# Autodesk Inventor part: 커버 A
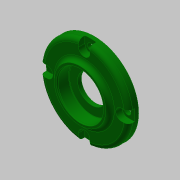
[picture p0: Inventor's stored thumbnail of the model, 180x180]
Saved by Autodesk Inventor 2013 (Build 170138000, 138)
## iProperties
Created: 2019-05
Part Number: 커버 A
Material: 알루미늄 6061
Document SubType Name: Modeling
Designer: mduedu
Density: 1 g/cm^3
Author: mduedu
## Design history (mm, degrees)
sketch "스케치1"
  geometry: C1 r 31 at (0, 0); 1 further point
  constraints: 1 centre point, 1 coincident
  dimensions: "d0" = 62 diameter of C1
extrude "돌출1" new body sketch "스케치1" distance "d1" = 7; taper "d2" = 0 deg
sketch "스케치2"
  geometry: C1 r 18 at (0, 0); 1 further point
  constraints: 1 centre point, 1 coincident
  dimensions: "d3" = 36 diameter of C1
extrude "돌출2" join sketch "스케치2" distance "d4" = 3; taper "d5" = 0 deg
fillet "모깎기1" dims "d6" = 3
sketch "스케치3"
  geometry: C1 r 20 at (0, 0); 1 further point
  constraints: 1 centre point, 1 coincident
  dimensions: "d7" = 40 diameter of C1
extrude "돌출3" join sketch "스케치3" distance "d8" = 4; taper "d9" = 0 deg
sketch "스케치4"
  geometry: C1 r 17 at (0, 0); 1 further point
  constraints: 1 centre point, 1 coincident
  dimensions: "d10" = 34 diameter of C1
extrude "돌출4" cut sketch "스케치4" distance "d11" = 3; taper "d12" = 0 deg
sketch "스케치5"
  geometry: C1 r 16 at (0, 0); 1 further point
  constraints: 1 centre point, 1 coincident
  dimensions: "d13" = 32 diameter of C1
extrude "돌출5" cut sketch "스케치5" distance "d14" = 8.3; taper "d15" = 0 deg
sketch "스케치6"
  geometry: C1 r 10 at (0, 0); 1 further point
  constraints: 1 centre point, 1 coincident
  dimensions: "d16" = 20 diameter of C1
extrude "돌출6" cut sketch "스케치6" stored distance "d17" = 8.3; taper "d18" = 0 deg
fillet "모깎기2" dims "d19" = 0.3
fillet "모깎기3" dims "d20" = 3
fillet "모깎기4" dims "d21" = 3
chamfer "모따기1" distance "d22" = 1; stored, may be unused: second distance "d23" = 2, angle "d24" = 45 deg
sketch "스케치7" dims "d25" = 52
  geometry: L1 (-4, 26)-(-4, 30.741); L2 (4, 26)-(4, 30.741); A1 r 4 centre (0, 26) between (-4, 26) and (4, 26); A2 r 31 centre (0, 0) between (4, 30.741) and (-4, 30.741); 3 further points
  constraints: 4 end point, 4 point on circle, 2 centre point, 2 coincident, 2 tangent, 2 vertical alignment, 1 parallel, 1 vertical, 4 other
  dimensions: "d26" = 8 distance between parallel lines of L2 L1
extrude "돌출7" cut sketch "스케치7" distance "d27" = 4.4; taper "d28" = 0 deg
chamfer "모따기2" distance "d32" = 0.8; stored, may be unused: second distance "d33" = 2, angle "d34" = 30 deg
sketch "스케치8" dims "d36" = 52
  geometry: 6 further points
  constraints: 2 vertical alignment, 1 coincident, 7 other
  dimensions: "d39" = 360 deg dimension on point (0, 0) point (0, 26) (derived)
sketch "스케치9"
  geometry: 4 further points
  constraints: 4 other
hole "구멍1" sketch "스케치9" at (-26, 0), (0, -26), (26, 0), (0, 26) diameter "d41" = 4.5; stored, may be unused: countersink angle "d45" = 90 deg, drill point angle "d47" = 0 deg; dims "d42" = 6, "d43" = 4, "d44" = 2, "d46" = 8
node "솔리드1"
pattern_circular "원형 패턴1" dims angle "d30" = 360 deg
